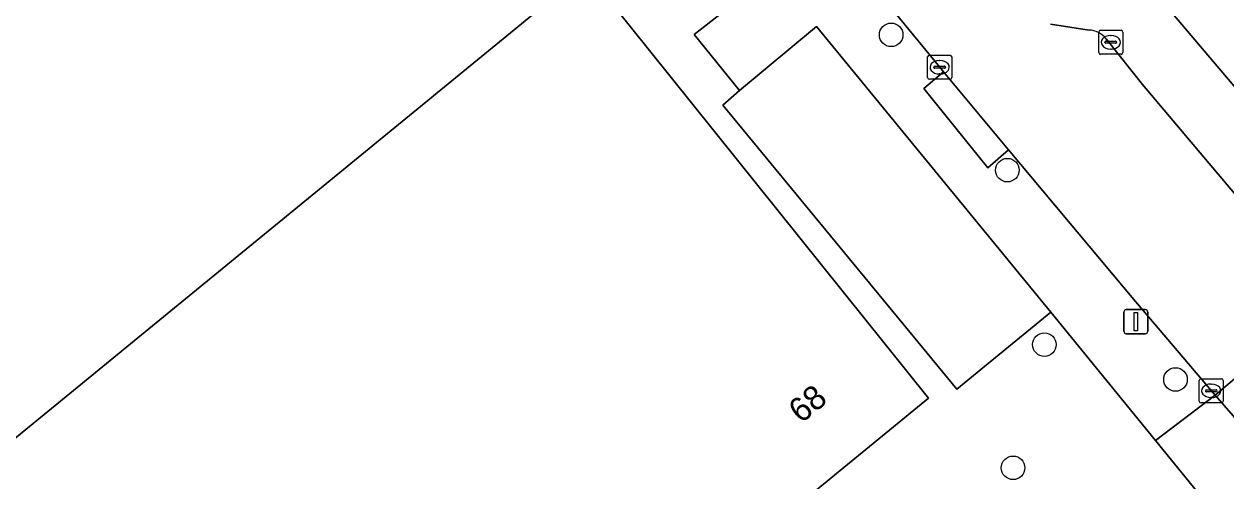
# Model space of a CAD drawing. Extents: x 162073 to 163043, y 381818 to 382561.
# Drawn here: x 162602.44 to 162652.37, y 381957.07 to 381976.06 of the extents above; entities that cross this region are included whole.
import ezdxf

# ---------------------------------------------------------------- set-up
doc = ezdxf.new("R2010")
doc.units = 0
for name, color, linetype in [('IMGEO_Boom', 7, 'Continuous'), ('IMGEO_Erf', 7, 'Continuous'), ('IMGEO_Kolk', 7, 'Continuous'), ('IMGEO_Lichtmast', 7, 'Continuous'), ('IMGEO_Muur', 7, 'Continuous'), ('IMGEO_Pand', 7, 'Continuous'), ('IMGEO_Pand_nummerreeks', 7, 'Continuous'), ('IMGEO_Parkeervlak_open', 7, 'Continuous'), ('IMGEO_Rijbaan_lokaal_open', 7, 'Continuous'), ('IMGEO_Voetpad_open', 7, 'Continuous')]:
    doc.layers.add(name, color=color, linetype=linetype)

msp = doc.modelspace()

# ---------------------------------------------------------------- linework, layer by layer
at = {"layer": 'IMGEO_Boom'}
for centre in [(162638.464, 381975.606), (162643.291, 381969.984), (162644.829, 381962.734), (162650.276, 381961.285), (162643.529, 381957.614)]:
    msp.add_circle(centre, 0.489, dxfattribs=at)
at = {"layer": 'IMGEO_Erf'}
for points in [[(162625.783, 381978.273), (162640.017, 381960.503), (162633.898, 381955.497), (162633.564, 381955.907), (162630.873, 381953.706), (162633.469, 381950.533), (162608.939, 381930.467), (162613.031, 381925.508), (162651.329, 381956.438), (162649.444, 381958.748), (162645.097, 381964.078), (162641.189, 381960.887), (162631.472, 381972.686), (162632.164, 381973.299), (162630.277, 381975.619), (162633.474, 381978.122), (162618.994, 381995.786), (162616.559, 381998.757), (162591.809, 382028.937), (162588.037, 382033.537), (162587.138, 382034.641)], [(162667.024, 382009.709), (162664.883, 382007.962), (162665.826, 382006.806), (162663.633, 382005.045), (162665.32, 382002.945), (162662.351, 382000.56), (162659.039, 381997.9), (162657.352, 382000), (162653.886, 381997.268), (162650.92, 381994.841), (162654.472, 381990.499), (162656.248, 381988.328), (162650.925, 381983.973), (162646.747, 381980.522), (162658.282, 381966.905)], [(162584.006, 381956.601), (162585.51, 381957.818), (162579.335, 381965.469), (162579.619, 381965.685), (162579.531, 381965.793), (162580.073, 381966.206), (162580.989, 381965.07), (162582.996, 381966.707), (162590.131, 381957.956), (162595.778, 381962.577), (162600.14, 381957.261), (162625.783, 381978.273)]]:
    msp.add_lwpolyline(points, dxfattribs=at)
at = {"layer": 'IMGEO_Kolk'}
for p, q in [((162647.161, 381975.797), (162648.013, 381975.797)), ((162647.086, 381974.871), (162647.086, 381975.723)), ((162647.345, 381975.291), (162647.345, 381975.303)), ((162647.388, 381975.34), (162647.786, 381975.34)), ((162647.574, 381975.577), (162647.599, 381975.577)), ((162647.829, 381975.303), (162647.829, 381975.291)), ((162648.087, 381975.723), (162648.087, 381974.871)), ((162648.013, 381974.797), (162647.161, 381974.797)), ((162647.783, 381975.254), (162647.385, 381975.254)), ((162647.597, 381975.017), (162647.572, 381975.017)), ((162639.978, 381973.834), (162639.978, 381974.686)), ((162640.053, 381974.76), (162640.905, 381974.76)), ((162640.28, 381974.303), (162640.678, 381974.303)), ((162640.466, 381974.54), (162640.491, 381974.54)), ((162640.979, 381974.686), (162640.979, 381973.834)), ((162640.237, 381974.254), (162640.237, 381974.266)), ((162640.675, 381974.217), (162640.277, 381974.217)), ((162640.489, 381973.98), (162640.464, 381973.98)), ((162640.721, 381974.266), (162640.721, 381974.254)), ((162640.905, 381973.76), (162640.053, 381973.76)), ((162651.336, 381961.313), (162652.188, 381961.313)), ((162651.261, 381960.387), (162651.261, 381961.239)), ((162651.52, 381960.807), (162651.52, 381960.819)), ((162651.563, 381960.856), (162651.961, 381960.856)), ((162651.749, 381961.093), (162651.774, 381961.093)), ((162652.004, 381960.819), (162652.004, 381960.807)), ((162652.262, 381961.239), (162652.262, 381960.387)), ((162652.188, 381960.313), (162651.336, 381960.313)), ((162651.958, 381960.77), (162651.56, 381960.77)), ((162651.772, 381960.533), (162651.747, 381960.533))]:
    msp.add_line(p, q, dxfattribs=at)
for points in [[(162647.161, 381975.797), (162648.013, 381975.797)], [(162647.086, 381974.871), (162647.086, 381975.723)], [(162648.087, 381975.723), (162648.087, 381974.871)], [(162648.013, 381974.797), (162647.161, 381974.797)], [(162639.978, 381973.834), (162639.978, 381974.686)], [(162640.053, 381974.76), (162640.905, 381974.76)], [(162640.979, 381974.686), (162640.979, 381973.834)], [(162640.905, 381973.76), (162640.053, 381973.76)], [(162651.336, 381961.313), (162652.188, 381961.313)], [(162651.261, 381960.387), (162651.261, 381961.239)], [(162652.262, 381961.239), (162652.262, 381960.387)], [(162652.188, 381960.313), (162651.336, 381960.313)]]:
    msp.add_lwpolyline(points, dxfattribs=at)
for centre, radius, start, end in [((162647.163, 381975.721), 0.0765, 91.552, 178.448), ((162647.163, 381975.721), 0.0765, 91.552, 178.448), ((162648.011, 381975.721), 0.0765, 1.552, 88.448), ((162648.011, 381975.721), 0.0765, 1.552, 88.448), ((162647.385, 381975.3), 0.0403, 85.8775, 175.7526), ((162647.382, 381975.29), 0.0366, 178.938, 274.7102), ((162647.786, 381975.297), 0.043, 264.8664, 352.4533), ((162647.79, 381975.302), 0.0386, 1.7309, 96.639), ((162647.163, 381974.873), 0.0765, 181.552, 268.448), ((162647.163, 381974.873), 0.0765, 181.552, 268.448), ((162648.011, 381974.873), 0.0765, 271.552, 358.448), ((162648.011, 381974.873), 0.0765, 271.552, 358.448), ((162640.055, 381974.684), 0.0765, 91.552, 178.448), ((162640.055, 381974.684), 0.0765, 91.552, 178.448), ((162640.277, 381974.263), 0.0403, 85.8775, 175.7526), ((162640.682, 381974.265), 0.0386, 1.7309, 96.639), ((162640.903, 381974.684), 0.0765, 1.552, 88.448), ((162640.903, 381974.684), 0.0765, 1.552, 88.448), ((162640.055, 381973.836), 0.0765, 181.552, 268.448), ((162640.055, 381973.836), 0.0765, 181.552, 268.448), ((162640.274, 381974.253), 0.0366, 178.938, 274.7102), ((162640.678, 381974.26), 0.043, 264.8664, 352.4533), ((162640.903, 381973.836), 0.0765, 271.552, 358.448), ((162640.903, 381973.836), 0.0765, 271.552, 358.448), ((162651.338, 381961.237), 0.0765, 91.552, 178.448), ((162651.338, 381961.237), 0.0765, 91.552, 178.448), ((162652.186, 381961.237), 0.0765, 1.552, 88.448), ((162652.186, 381961.237), 0.0765, 1.552, 88.448), ((162651.56, 381960.816), 0.0403, 85.8775, 175.7526), ((162651.557, 381960.806), 0.0366, 178.938, 274.7102), ((162651.961, 381960.813), 0.043, 264.8664, 352.4533), ((162651.965, 381960.818), 0.0386, 1.7309, 96.639), ((162651.338, 381960.389), 0.0765, 181.552, 268.448), ((162651.338, 381960.389), 0.0765, 181.552, 268.448), ((162652.186, 381960.389), 0.0765, 271.552, 358.448), ((162652.186, 381960.389), 0.0765, 271.552, 358.448)]:
    msp.add_arc(centre, radius, start, end, dxfattribs=at)
for centre, major_axis, ratio, start_param, end_param in [((162647.573, 381975.297), (-0.387, 0.002), 0.722429, 4.712389, 7.853982), ((162647.598, 381975.297), (-0.39, 0.002), 0.717154, 1.570796, 4.712389), ((162640.465, 381974.26), (-0.387, 0.002), 0.722429, 4.712389, 7.853982), ((162640.49, 381974.26), (-0.39, 0.002), 0.717154, 1.570796, 4.712389), ((162651.748, 381960.813), (-0.387, 0.002), 0.722429, 4.712389, 7.853982), ((162651.773, 381960.813), (-0.39, 0.002), 0.717154, 1.570796, 4.712389)]:
    msp.add_ellipse(centre, major_axis=major_axis, ratio=ratio, start_param=start_param, end_param=end_param, dxfattribs=at)
at = {"layer": 'IMGEO_Lichtmast'}
for p, q in [((162648.132, 381963.287), (162648.132, 381964.087)), ((162648.132, 381964.087), (162648.132, 381963.287)), ((162648.232, 381964.187), (162649.022, 381964.187)), ((162649.022, 381964.187), (162648.232, 381964.187)), ((162649.122, 381964.087), (162649.122, 381963.287)), ((162649.122, 381963.287), (162649.122, 381964.087)), ((162649.022, 381963.187), (162648.232, 381963.187)), ((162648.232, 381963.187), (162649.022, 381963.187))]:
    msp.add_line(p, q, dxfattribs=at)
msp.add_lwpolyline([(162648.552, 381964.062), (162648.702, 381964.062), (162648.702, 381963.312), (162648.552, 381963.312), (162648.552, 381964.062)], dxfattribs=at)
for centre, start, end in [((162648.232, 381964.087), 90, 180), ((162648.232, 381964.087), 90, 180), ((162649.022, 381964.087), 0, 90), ((162649.022, 381964.087), 360, 90), ((162648.232, 381963.287), 180, 270), ((162648.232, 381963.287), 180, 270), ((162649.022, 381963.287), 270, 0), ((162649.022, 381963.287), 270, 0)]:
    msp.add_arc(centre, 0.1, start, end, dxfattribs=at)
at = {"layer": 'IMGEO_Muur'}
msp.add_lwpolyline([(162658.282, 381966.905), (162646.747, 381980.522)], dxfattribs=at)
at = {"layer": 'IMGEO_Pand'}
msp.add_lwpolyline([(162608.939, 381930.467), (162633.469, 381950.533), (162630.873, 381953.706), (162633.564, 381955.907), (162633.898, 381955.497), (162640.017, 381960.503), (162625.783, 381978.273), (162600.14, 381957.261), (162595.778, 381962.577), (162590.131, 381957.956), (162582.996, 381966.707), (162580.989, 381965.07), (162580.873, 381964.976), (162581.57, 381964.121), (162586.627, 381957.92), (162589.722, 381954.124), (162594.392, 381948.398), (162594.733, 381948.676), (162596.627, 381946.361), (162596.286, 381946.083), (162596.393, 381945.952), (162598.107, 381943.844), (162605.386, 381934.855), (162605.792, 381934.353)], close=True, dxfattribs=at)
at = {"layer": 'IMGEO_Parkeervlak_open'}
msp.add_lwpolyline([(162635.369, 381975.951), (162632.164, 381973.299), (162631.472, 381972.686), (162641.189, 381960.887), (162645.097, 381964.078)], close=True, dxfattribs=at)
at = {"layer": 'IMGEO_Rijbaan_lokaal_open'}
for points in [[(162597.614, 382026.5), (162606.791, 382015.289), (162614.144, 382006.402), (162615.508, 382004.754), (162617.368, 382002.476), (162619.379, 382000), (162627.42, 381990.159), (162640.48, 381974.261), (162640.64, 381974.07), (162643.345, 381970.833), (162648.612, 381964.53), (162651.367, 381961.278), (162651.92, 381960.627), (162656.461, 381964.469), (162654.597, 381966.796), (162648.908, 381973.547), (162647.391, 381975.444)], [(162646.689, 381975.806), (162645.086, 381976.056)], [(162656.461, 381964.469), (162651.92, 381960.627), (162652.677, 381959.774)]]:
    msp.add_lwpolyline(points, dxfattribs=at)
msp.add_arc((162646.635, 381974.84), 0.967, 38.6298, 86.8127, dxfattribs=at)
at = {"layer": 'IMGEO_Voetpad_open'}
for points in [[(162648.612, 381964.53), (162643.345, 381970.833), (162642.476, 381970.081), (162639.826, 381973.372), (162640.64, 381974.07), (162640.48, 381974.261), (162627.42, 381990.159), (162619.379, 382000), (162617.368, 382002.476), (162616.983, 382002.159), (162613.753, 382006.08), (162614.144, 382006.402), (162606.791, 382015.289), (162597.614, 382026.5), (162597.268, 382026.923), (162594.105, 382030.795), (162593.025, 382032.116), (162592.645, 382031.792), (162589.67, 382035.273), (162590.05, 382035.597)], [(162587.138, 382034.641), (162588.037, 382033.537), (162591.809, 382028.937), (162616.559, 381998.757), (162618.994, 381995.786), (162633.474, 381978.122), (162630.277, 381975.619), (162632.164, 381973.299), (162635.369, 381975.951), (162645.097, 381964.078), (162649.444, 381958.748), (162651.92, 381960.627), (162651.367, 381961.278), (162648.612, 381964.53)], [(162647.391, 381975.444), (162648.908, 381973.547), (162654.597, 381966.796), (162656.461, 381964.469), (162658.282, 381966.905), (162646.747, 381980.522)], [(162645.086, 381976.056), (162646.689, 381975.806)], [(162653.907, 381957.009), (162653.8, 381957.534), (162653.647, 381958.04), (162653.454, 381958.52), (162653.224, 381958.971), (162652.963, 381959.39), (162652.677, 381959.774), (162651.92, 381960.627), (162649.444, 381958.748), (162651.329, 381956.438)]]:
    msp.add_lwpolyline(points, dxfattribs=at)
msp.add_lwpolyline([(162643.345, 381970.833), (162640.64, 381974.07), (162639.826, 381973.372), (162642.476, 381970.081)], close=True, dxfattribs=at)
msp.add_arc((162646.635, 381974.84), 0.967, 38.6298, 86.8127, dxfattribs=at)

# ---------------------------------------------------------------- texts
at = {"layer": 'IMGEO_Pand_nummerreeks'}
msp.add_text('68', height=1, rotation=39.2869, dxfattribs=at).set_placement((162634.725, 381959.429))

doc.saveas('drawing.dxf')
